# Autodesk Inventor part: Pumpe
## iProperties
Created: 2005-10
Part Number: Pumpe
Document SubType Name: Modeling
Designer: rsc
Manufacturer: Standard
Standards Organization: Custom
Author: rsc
Kanten: brechen
Oberflächen: Ra 3,2
Radien: 2
Toleranzen: ISO 2768 - m
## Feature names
1. Extrusion1
